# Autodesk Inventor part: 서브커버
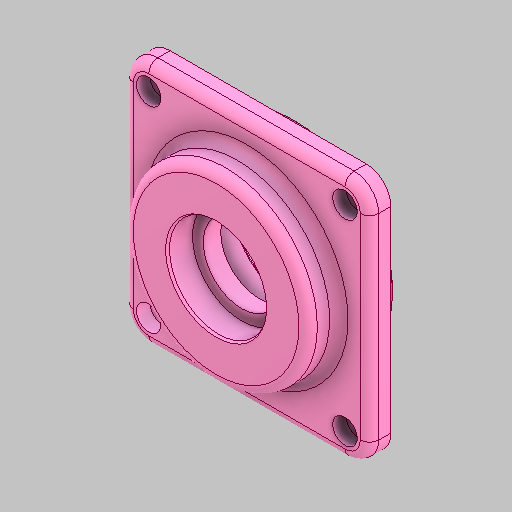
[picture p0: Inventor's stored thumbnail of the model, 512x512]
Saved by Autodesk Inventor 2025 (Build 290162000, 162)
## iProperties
Created: 2024-08
Part Number: 서브커버
Material: 알루미늄 6061
Document SubType Name: Modeling
Designer: 현기
Density: 2.7 g/cm^3
Appearance: 알루미늄 - 평지
Mass: 205.778 g
Surface Area: 196.569 cm^2
Volume: 76.2142 cm^3
Sending System: Autodesk Inventor 2025
Preprocessor: ST-DEVELOPER v20
Author: jhkim
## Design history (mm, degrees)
feature "솔리드1"
node "솔리드2"
